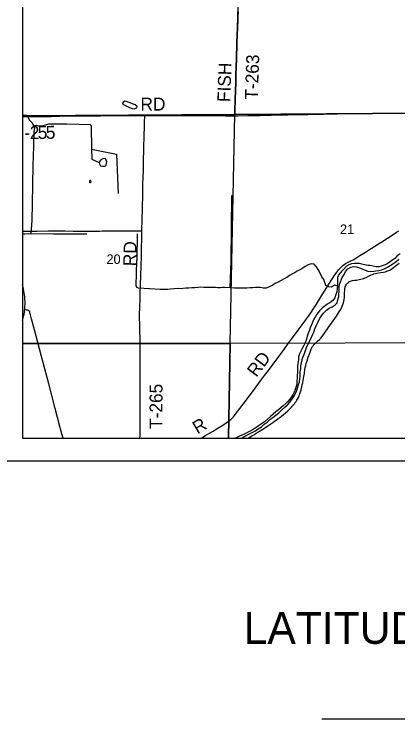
# Model space of a CAD drawing. Extents: x 0 to 34, y 0 to 22.
# Drawn here: x 2.063 to 3.748, y 12.866 to 15.963 of the extents above; entities that cross this region are included whole.
import ezdxf

# ---------------------------------------------------------------- set-up
doc = ezdxf.new("R2010")
doc.units = 0
for name, color, linetype in [('Default', 7, 'Continuous'), ('GM_X_County_Road', 7, 'Continuous'), ('GM_X_County_Road_Text', 7, 'Continuous'), ('GM_X_Major_River', 7, 'Continuous'), ('GM_X_Minor_Lake', 7, 'Continuous'), ('GM_X_Minor_River', 7, 'Continuous'), ('GM_X_Section', 7, 'Continuous'), ('GM_X_Section_Text', 7, 'Continuous'), ('GM_X_State_Route', 7, 'Continuous'), ('GM_X_Township_Road', 7, 'Continuous'), ('GM_X_Township_Road_Text', 7, 'Continuous'), ('SH_Cut_Line', 7, 'Continuous'), ('SH_Data', 7, 'Continuous'), ('SH_Text', 7, 'Continuous')]:
    doc.layers.add(name, color=color, linetype=linetype)

msp = doc.modelspace()

# ---------------------------------------------------------------- linework, layer by layer
at = {"layer": 'Default'}
for points in [[(2.1, 20.9), (2.1, 15.5125), (2.1335, 15.5129), (2.1815, 15.5136), (2.2258, 15.5141), (2.2457, 15.5144), (2.2639, 15.5151), (2.2983, 15.5158), (2.3231, 15.516), (2.3339, 15.516), (2.343, 15.516), (2.3476, 15.5161), (2.3661, 15.5163), (2.3832, 15.5166), (2.4025, 15.5166), (2.4222, 15.5167), (2.4426, 15.5165), (2.4906, 15.5172), (2.5125, 15.5174), (2.5402, 15.5177), (2.5775, 15.5177), (2.6024, 15.5175), (2.6303, 15.5178), (2.6364, 15.5178), (2.6552, 15.518), (2.719, 15.5177), (2.7423, 15.5176), (2.7734, 15.5174), (2.8138, 15.5174), (2.8667, 15.5172), (2.9429, 15.5172), (2.9911, 15.517), (3.0253, 15.5169), (3.0312, 15.5169), (3.0315, 15.5224), (3.0323, 15.5411), (3.0338, 15.5877), (3.0363, 15.6623), (3.0371, 15.6965), (3.038, 15.7308), (3.0394, 15.7681), (3.0416, 15.8334), (3.043, 15.877), (3.0437, 15.8954), (3.0439, 15.9013), (3.0443, 15.9135), (3.0446, 15.9228), (3.0452, 15.9414), (3.0454, 15.9508), (3.0461, 15.9726)], [(3.0461, 15.9726), (3.0454, 15.9508), (3.0452, 15.9414), (3.0446, 15.9228), (3.0443, 15.9135), (3.0439, 15.9013), (3.0437, 15.8954), (3.043, 15.877), (3.0416, 15.8334), (3.0394, 15.7681), (3.038, 15.7308), (3.0371, 15.6965), (3.0363, 15.6623), (3.0338, 15.5877), (3.0323, 15.5411), (3.0315, 15.5224), (3.0312, 15.5169), (3.0253, 15.5169), (2.9911, 15.517), (2.9429, 15.5172), (2.8667, 15.5172), (2.8138, 15.5174), (2.7734, 15.5174), (2.7423, 15.5176), (2.719, 15.5177), (2.6552, 15.518), (2.6364, 15.5178), (2.6303, 15.5178), (2.6024, 15.5175), (2.5775, 15.5177), (2.5402, 15.5177), (2.5125, 15.5174), (2.4906, 15.5172), (2.4426, 15.5165), (2.4222, 15.5167), (2.4025, 15.5166), (2.3832, 15.5166), (2.3661, 15.5163), (2.3476, 15.5161), (2.343, 15.516), (2.3339, 15.516), (2.3231, 15.516), (2.2983, 15.5158), (2.2639, 15.5151), (2.2457, 15.5144), (2.2258, 15.5141), (2.1815, 15.5136), (2.1335, 15.5129), (2.1, 15.5125), (2.1, 14.1), (7.0155, 14.1)]]:
    msp.add_lwpolyline(points, dxfattribs=at)
for points in [[(2.1, 16.5162), (2.1, 15.5152), (3.0319, 15.521), (3.0627, 16.5204)], [(2.1, 15.5152), (2.1, 14.516), (3.0117, 14.5162), (3.0319, 15.521)], [(2.1, 14.516), (2.1, 14.1), (3.005, 14.1), (3.0117, 14.5162)], [(3.005, 14.1), (4.0075, 14.1), (4.0206, 14.5179), (3.0117, 14.5162)]]:
    msp.add_lwpolyline(points, close=True, dxfattribs=at)
at = {"layer": 'GM_X_County_Road'}
for points in [[(2.8851, 14.1), (2.9051, 14.112), (2.9365, 14.1309), (2.954, 14.1416), (2.9788, 14.157), (2.9944, 14.1672), (3.0041, 14.1738), (3.01, 14.1783), (3.0148, 14.1823), (3.0198, 14.1869), (3.0258, 14.1931), (3.031, 14.1992), (3.0387, 14.2089), (3.0539, 14.2294), (3.0686, 14.2494), (3.0871, 14.2736), (3.0994, 14.29), (3.1142, 14.3093), (3.1376, 14.3406), (3.1495, 14.3566), (3.1628, 14.3746), (3.1796, 14.397), (3.2, 14.4244), (3.2251, 14.4585), (3.247, 14.4879), (3.2669, 14.515), (3.2943, 14.5519), (3.3102, 14.5734), (3.3274, 14.597), (3.3443, 14.6201), (3.3557, 14.6363), (3.3656, 14.6506), (3.3763, 14.6667), (3.3903, 14.6887), (3.4133, 14.7256), (3.4289, 14.7503), (3.4453, 14.7768), (3.4611, 14.8013), (3.4716, 14.8168), (3.4816, 14.8311), (3.4872, 14.8386), (3.4928, 14.8453), (3.4971, 14.8499), (3.5016, 14.8543), (3.5069, 14.8587), (3.5124, 14.8628), (3.5182, 14.8666), (3.5237, 14.8696), (3.533, 14.8742), (3.5437, 14.8797), (3.5513, 14.8838), (3.5631, 14.8906), (3.5811, 14.9018), (3.5984, 14.9127), (3.6105, 14.9204), (3.6194, 14.926), (3.671, 14.9584), (3.6731, 14.9598), (3.7025, 14.9785), (3.7271, 14.9942), (3.7427, 15.0044), (3.7516, 15.0102)], [(2.2777, 14.1), (2.2729, 14.1179), (2.2643, 14.151), (2.2437, 14.2293), (2.2286, 14.2864), (2.2152, 14.3376), (2.1978, 14.4039), (2.1819, 14.4641), (2.1523, 14.5753), (2.1396, 14.6235), (2.1349, 14.6415), (2.1325, 14.6506), (2.1314, 14.6537), (2.1301, 14.6571), (2.1282, 14.6594), (2.125, 14.6614), (2.1221, 14.6622), (2.1186, 14.6625), (2.1154, 14.6626), (2.109, 14.6629)]]:
    msp.add_lwpolyline(points, dxfattribs=at)
at = {"layer": 'GM_X_Major_River'}
for points in [[(3.7575, 14.9091), (3.7451, 14.9003), (3.7346, 14.8888), (3.7015, 14.8652)], [(3.7015, 14.8652), (3.6919, 14.8608), (3.6793, 14.8564), (3.6659, 14.8525), (3.653, 14.8527), (3.6398, 14.8548), (3.6265, 14.8576), (3.617, 14.8586), (3.6034, 14.8618), (3.5894, 14.8647), (3.5796, 14.8664), (3.5572, 14.8667), (3.545, 14.865), (3.5324, 14.8614), (3.5224, 14.8551), (3.5108, 14.8424), (3.4992, 14.83), (3.4889, 14.8186), (3.4834, 14.8051), (3.4831, 14.7934), (3.4829, 14.7805), (3.4829, 14.7678), (3.4822, 14.757), (3.4793, 14.743), (3.4757, 14.7301), (3.4709, 14.7165), (3.4627, 14.7045), (3.4489, 14.6945), (3.4382, 14.6882), (3.4282, 14.6807), (3.4166, 14.6722), (3.4035, 14.6587), (3.3919, 14.6448), (3.3861, 14.6347), (3.379, 14.623), (3.3739, 14.6124), (3.3681, 14.598), (3.3636, 14.5845), (3.3604, 14.5743), (3.3545, 14.5615), (3.3501, 14.5483), (3.3465, 14.5339), (3.3406, 14.518), (3.3347, 14.506), (3.3284, 14.4939), (3.3221, 14.4819), (3.3159, 14.4694), (3.3123, 14.4563), (3.3113, 14.4437), (3.3084, 14.4281), (3.3074, 14.4171), (3.3069, 14.4073), (3.3075, 14.3955), (3.3066, 14.386), (3.3061, 14.3762), (3.3063, 14.3636), (3.3049, 14.3519), (3.304, 14.3394), (3.3011, 14.3269), (3.2975, 14.3136), (3.2928, 14.3019), (3.2861, 14.2906), (3.2775, 14.2767), (3.2656, 14.2625), (3.257, 14.2527), (3.2439, 14.2412), (3.2359, 14.2349), (3.2235, 14.2245), (3.2124, 14.2151), (3.2009, 14.205), (3.1893, 14.1942), (3.1758, 14.1837), (3.1624, 14.1718), (3.1493, 14.1618), (3.1366, 14.1532), (3.1247, 14.1451), (3.1094, 14.1358), (3.0998, 14.1306), (3.0879, 14.1247), (3.0757, 14.1185), (3.0627, 14.1122), (3.0497, 14.1063), (3.0378, 14.1008), (3.0353, 14.1)], [(3.5789, 14.8474), (3.5917, 14.8434), (3.6042, 14.8375), (3.6167, 14.8331), (3.6295, 14.8324), (3.6421, 14.8339), (3.6516, 14.8349), (3.6642, 14.8366), (3.6771, 14.8394), (3.6901, 14.8453), (3.7024, 14.8508), (3.7146, 14.8578), (3.7265, 14.8656)], [(3.7265, 14.8656), (3.74, 14.8761), (3.752, 14.8857)], [(3.0619, 14.1), (3.0647, 14.1011), (3.0763, 14.1078), (3.0882, 14.1149), (3.0996, 14.1204), (3.1111, 14.1266), (3.123, 14.1325), (3.1353, 14.1407), (3.1488, 14.1496), (3.1614, 14.1604), (3.1737, 14.1705), (3.186, 14.1809), (3.1983, 14.1902), (3.2122, 14.201), (3.2249, 14.2107), (3.2376, 14.2227), (3.2511, 14.2354), (3.2634, 14.2462), (3.2742, 14.2578), (3.2831, 14.2698), (3.2913, 14.2826), (3.2966, 14.2928), (3.3031, 14.3063), (3.3075, 14.3199), (3.3119, 14.3351), (3.3159, 14.3471), (3.318, 14.3608), (3.3189, 14.3703), (3.3191, 14.3813), (3.3196, 14.3908), (3.3217, 14.4036), (3.3226, 14.4162), (3.3235, 14.4256), (3.3264, 14.4358), (3.3296, 14.451), (3.3348, 14.4638), (3.3395, 14.4755), (3.3439, 14.4891), (3.3471, 14.4989), (3.3522, 14.5099), (3.3573, 14.52), (3.3632, 14.5302), (3.3687, 14.5434), (3.373, 14.5532), (3.3785, 14.5657), (3.3833, 14.5793), (3.391, 14.5964), (3.3963, 14.6079), (3.4045, 14.6245), (3.4123, 14.6369), (3.4212, 14.6493), (3.4343, 14.6613), (3.447, 14.6709), (3.46, 14.6772), (3.4721, 14.6848), (3.481, 14.6946), (3.4848, 14.7068), (3.4881, 14.7227), (3.489, 14.7326), (3.4896, 14.7457), (3.4898, 14.7572), (3.4907, 14.7675), (3.4935, 14.7792), (3.5041, 14.806), (3.5116, 14.8188), (3.5183, 14.8312), (3.5276, 14.844), (3.541, 14.8506), (3.5528, 14.8535), (3.5657, 14.8529), (3.5789, 14.8474)]]:
    msp.add_lwpolyline(points, dxfattribs=at)
at = {"layer": 'GM_X_Minor_Lake'}
for p, q in [((2.5829, 15.5692), (2.5748, 15.5713)), ((2.4422, 15.2965), (2.4516, 15.2947)), ((2.3933, 15.227), (2.3941, 15.2236))]:
    msp.add_line(p, q, dxfattribs=at)
for points in [[(2.5748, 15.5713), (2.5678, 15.5738), (2.5569, 15.5791), (2.5498, 15.5808), (2.5417, 15.5765), (2.5388, 15.5678), (2.5463, 15.5642), (2.5702, 15.5525), (2.5807, 15.5484), (2.5894, 15.547), (2.6013, 15.5508), (2.6034, 15.5565), (2.5949, 15.5643), (2.5829, 15.5692)], [(2.4516, 15.2947), (2.4623, 15.2947), (2.4678, 15.2992), (2.4708, 15.3131), (2.464, 15.3282), (2.4522, 15.3266), (2.4418, 15.3204), (2.437, 15.3107), (2.4383, 15.3046), (2.4422, 15.2965)], [(2.3941, 15.2236), (2.3973, 15.2229), (2.4019, 15.2254), (2.3998, 15.2323), (2.3956, 15.2316), (2.3933, 15.2294), (2.3933, 15.227)]]:
    msp.add_lwpolyline(points, dxfattribs=at)
at = {"layer": 'GM_X_Minor_River'}
for points in [[(2.1, 15.5185), (2.1195, 15.5186), (2.1248, 15.5075), (2.131, 15.4963), (2.1402, 15.4861), (2.15, 15.4706), (2.1531, 15.4603), (2.1494, 15.449), (2.1486, 15.3809), (2.1458, 15.2985), (2.1434, 15.2126), (2.1415, 15.131), (2.1401, 15.0561), (2.1365, 14.9984)], [(2.15, 15.4706), (2.1546, 15.4735), (2.1615, 15.4745), (2.169, 15.4716), (2.1773, 15.4714), (2.1899, 15.474), (2.201, 15.4764), (2.2156, 15.4805), (2.2432, 15.4801), (2.296, 15.4809), (2.3984, 15.4772), (2.4016, 15.4699), (2.4029, 15.3687), (2.4043, 15.3249), (2.437, 15.3107)], [(2.4029, 15.3687), (2.5124, 15.3481), (2.5192, 15.1741)], [(3.0164, 14.8785), (3.019, 15.1657)], [(2.1, 14.9977), (2.1107, 14.9976), (2.1365, 14.9984), (2.236, 14.9971), (2.3821, 14.9974)], [(2.6034, 14.9968), (2.6012, 14.8801)], [(2.7052, 14.7533), (2.6089, 14.7584), (2.6029, 14.7616), (2.5984, 14.7685), (2.6012, 14.8801)], [(3.4829, 14.7678), (3.4691, 14.7717), (3.4564, 14.7637), (3.4431, 14.7641), (3.4315, 14.7702), (3.4277, 14.784), (3.4227, 14.797), (3.4147, 14.809), (3.409, 14.8213), (3.3974, 14.8407), (3.3905, 14.853), (3.3806, 14.8647), (3.3673, 14.8655), (3.3543, 14.8613), (3.3412, 14.8533), (3.3307, 14.8464), (3.3172, 14.8388), (3.3064, 14.8334), (3.2967, 14.828), (3.2855, 14.8215), (3.2728, 14.8143), (3.26, 14.8059), (3.2453, 14.7976), (3.2357, 14.7922), (3.2222, 14.7854), (3.2098, 14.7793), (3.1959, 14.7709), (3.1824, 14.7641), (3.1693, 14.7592), (3.1564, 14.7584), (3.1443, 14.761), (3.1326, 14.7618), (3.1223, 14.7617), (3.1097, 14.7605), (3.0976, 14.7605), (3.085, 14.7593), (3.0721, 14.759), (3.0573, 14.759), (3.0428, 14.7587), (3.0307, 14.759), (3.0166, 14.7602), (2.9874, 14.761), (2.9779, 14.7609), (2.9672, 14.7605), (2.957, 14.7604), (2.9467, 14.7611), (2.9327, 14.7615), (2.9213, 14.7611), (2.9103, 14.7618), (2.8959, 14.7622), (2.8833, 14.7629), (2.8696, 14.7618), (2.8567, 14.7607), (2.8426, 14.7596), (2.8304, 14.7588), (2.8167, 14.758), (2.8045, 14.7572), (2.7927, 14.7564), (2.779, 14.7565), (2.7657, 14.7553), (2.7501, 14.7539), (2.7375, 14.7535), (2.7261, 14.7531), (2.7159, 14.7534), (2.7052, 14.7533)], [(3.0118, 14.7603), (3.0164, 14.8785)]]:
    msp.add_lwpolyline(points, dxfattribs=at)
at = {"layer": 'GM_X_Section'}
for points in [[(3.0627, 16.5204), (4.0656, 16.5335), (4.0396, 15.5284), (3.0319, 15.521)], [(4.0396, 15.5284), (4.0206, 14.5179), (3.0117, 14.5162), (3.0319, 15.521)]]:
    msp.add_lwpolyline(points, close=True, dxfattribs=at)
at = {"layer": 'GM_X_State_Route'}
msp.add_lwpolyline([(2.1, 14.6166), (2.1019, 14.6232), (2.1044, 14.6338), (2.1065, 14.6445), (2.1081, 14.6553), (2.109, 14.6629), (2.1094, 14.6662), (2.1103, 14.6771), (2.1108, 14.688), (2.1108, 14.6989), (2.1104, 14.7098), (2.1095, 14.7207), (2.1082, 14.7315), (2.1063, 14.7438), (2.1043, 14.7545), (2.1012, 14.7682), (2.1, 14.773)], dxfattribs=at)
at = {"layer": 'GM_X_Township_Road'}
for points in [[(3.0314, 15.5164), (3.0317, 15.5219), (3.0325, 15.5405), (3.034, 15.5872), (3.0366, 15.6618), (3.0373, 15.696), (3.0383, 15.7302), (3.0397, 15.7676), (3.0418, 15.8329), (3.0432, 15.8764), (3.0439, 15.8948), (3.0441, 15.9007), (3.0446, 15.9129), (3.0448, 15.9222), (3.0454, 15.9409), (3.0457, 15.9502), (3.0463, 15.972)], [(2.1, 15.5119), (2.1337, 15.5124), (2.1818, 15.513), (2.226, 15.5136), (2.2459, 15.5139), (2.2642, 15.5146), (2.2986, 15.5152), (2.3233, 15.5154), (2.3342, 15.5154), (2.3433, 15.5154), (2.3478, 15.5156), (2.3663, 15.5158), (2.3834, 15.516), (2.4027, 15.5161), (2.4224, 15.5161), (2.4428, 15.5159), (2.4909, 15.5166), (2.5127, 15.5168), (2.5305, 15.517)], [(2.5305, 15.517), (2.5404, 15.5171), (2.5777, 15.5171), (2.6026, 15.517), (2.6306, 15.5172), (2.6366, 15.5173)], [(2.6244, 15.0111), (2.6244, 15.0132), (2.6267, 15.1079), (2.627, 15.1219), (2.6277, 15.1577), (2.6277, 15.1732), (2.6276, 15.1841), (2.6276, 15.1918), (2.6278, 15.2027), (2.6285, 15.2198), (2.6294, 15.2415), (2.6304, 15.2804), (2.6309, 15.3037), (2.6316, 15.3332), (2.632, 15.3518), (2.6322, 15.3611), (2.6326, 15.3767), (2.6342, 15.4264), (2.6353, 15.4683), (2.6359, 15.4916), (2.6365, 15.5117), (2.6366, 15.5173)], [(2.6366, 15.5173), (2.6554, 15.5174), (2.7192, 15.5171), (2.7425, 15.517), (2.7736, 15.5169), (2.814, 15.5168), (2.8669, 15.5167), (2.9431, 15.5166), (2.9913, 15.5165), (3.0255, 15.5164), (3.0314, 15.5164)], [(3.0314, 15.5164), (3.0473, 15.5163), (3.0892, 15.5169), (3.1219, 15.5176), (3.1436, 15.5179), (3.1624, 15.5182), (3.1918, 15.5189), (3.2369, 15.5198), (3.2648, 15.5204), (3.3069, 15.5211), (3.352, 15.5216), (3.4218, 15.5235), (3.5415, 15.5257), (3.582, 15.5262), (3.6333, 15.5268), (3.6908, 15.5275), (3.7545, 15.5278), (3.8105, 15.5282), (3.9131, 15.5284), (3.9567, 15.5287), (3.9987, 15.5291), (4.0375, 15.5293), (4.0423, 15.5293)], [(2.1, 15.0091), (2.1116, 15.0092), (2.1644, 15.0095), (2.214, 15.0102), (2.2513, 15.0101), (2.2854, 15.0099), (2.3226, 15.0096), (2.3351, 15.0096), (2.3816, 15.0095), (2.4249, 15.0096), (2.4373, 15.0097), (2.4497, 15.0099), (2.4621, 15.0101), (2.4838, 15.0102), (2.4962, 15.0101), (2.5116, 15.0101), (2.5146, 15.0101), (2.5207, 15.0103), (2.5268, 15.0104), (2.5391, 15.0105), (2.5515, 15.0107), (2.5825, 15.0109), (2.6104, 15.011), (2.6198, 15.0111), (2.6244, 15.0111)], [(2.6157, 14.1), (2.6158, 14.1105), (2.6161, 14.1385), (2.6164, 14.1898), (2.6163, 14.2364), (2.6165, 14.2831), (2.6166, 14.3173), (2.6166, 14.4027), (2.6165, 14.4463), (2.6164, 14.4882), (2.6163, 14.5115), (2.6158, 14.5395), (2.6152, 14.569), (2.6145, 14.6047), (2.6142, 14.6218), (2.614, 14.6327), (2.6139, 14.642), (2.6141, 14.6513), (2.6145, 14.6652), (2.6149, 14.6776), (2.6159, 14.704), (2.617, 14.7382), (2.6183, 14.7739), (2.6195, 14.8127), (2.6207, 14.8578), (2.6216, 14.8998), (2.6244, 15.0111)], [(3.0902, 14.1), (3.0925, 14.1011), (3.1074, 14.1095), (3.1181, 14.1159), (3.126, 14.1208), (3.1366, 14.1273), (3.155, 14.139), (3.1641, 14.1449), (3.177, 14.1536), (3.1988, 14.1685), (3.2102, 14.1765), (3.214, 14.1792), (3.2229, 14.1855), (3.2279, 14.1891), (3.2316, 14.192), (3.2437, 14.2018), (3.2544, 14.2108), (3.2648, 14.2201), (3.2749, 14.2298), (3.2804, 14.2354), (3.2845, 14.2401), (3.2887, 14.2447), (3.2936, 14.2508), (3.2973, 14.2558), (3.3008, 14.261), (3.3042, 14.2662), (3.3066, 14.2703), (3.311, 14.2786), (3.3141, 14.2857), (3.3163, 14.2916), (3.3173, 14.2945), (3.3202, 14.3034), (3.3228, 14.3124), (3.3259, 14.3244), (3.3284, 14.335), (3.33, 14.3426), (3.3325, 14.3548), (3.3352, 14.3702), (3.3375, 14.384), (3.3401, 14.4008), (3.3427, 14.4145), (3.3437, 14.4191), (3.346, 14.4281), (3.3495, 14.4399), (3.3548, 14.4561), (3.361, 14.4737), (3.366, 14.4868), (3.3678, 14.491), (3.3705, 14.4965), (3.3736, 14.5018), (3.3771, 14.5069), (3.38, 14.5104), (3.3864, 14.5171), (3.3952, 14.5258), (3.4032, 14.5329), (3.4093, 14.5395), (3.4143, 14.5453), (3.4195, 14.5517), (3.4323, 14.5701), (3.4496, 14.595), (3.4634, 14.6147), (3.4782, 14.6356), (3.4879, 14.6504), (3.493, 14.6585), (3.497, 14.6654), (3.5002, 14.6723), (3.5037, 14.6794), (3.5063, 14.6866), (3.5086, 14.6942), (3.5109, 14.7016), (3.5121, 14.7093), (3.5132, 14.717), (3.5138, 14.7266), (3.5144, 14.7343), (3.5144, 14.7375), (3.5145, 14.7499), (3.5147, 14.7545), (3.5152, 14.759), (3.5159, 14.762), (3.5168, 14.7649), (3.5185, 14.7691), (3.5206, 14.7731), (3.5223, 14.7756), (3.5252, 14.7791), (3.5273, 14.7813), (3.5308, 14.7842), (3.5334, 14.7859), (3.536, 14.7874), (3.5402, 14.7892), (3.5445, 14.7908), (3.549, 14.7919), (3.5579, 14.7932), (3.5671, 14.7945), (3.5778, 14.7962), (3.5856, 14.7978), (3.5918, 14.7993), (3.5976, 14.8011), (3.6035, 14.8034), (3.6093, 14.8057), (3.6191, 14.8107), (3.6247, 14.8138), (3.6306, 14.8166), (3.6371, 14.8191), (3.6431, 14.8212), (3.6491, 14.823), (3.655, 14.8242), (3.6717, 14.8271), (3.6856, 14.8293), (3.6932, 14.8308), (3.6993, 14.8326), (3.7037, 14.8342), (3.708, 14.836), (3.7122, 14.8382), (3.7177, 14.8413), (3.7229, 14.8447), (3.7292, 14.8494), (3.7365, 14.8552), (3.7412, 14.8589), (3.7474, 14.8635), (3.7537, 14.8678)]]:
    msp.add_lwpolyline(points, dxfattribs=at)
at = {"layer": 'SH_Cut_Line'}
msp.add_lwpolyline([(2.1, 20.9), (2.1, 14.1), (7.0155, 14.1)], dxfattribs=at)
at = {"layer": 'SH_Data'}
for p, q in [((2.1, 20.9), (2.1, 14.1)), ((2.1, 14.1), (8.9, 14.1)), ((2.1, 14.1), (2.1, 14.1)), ((2, 14), (9, 14)), ((3.4138, 12.866), (4.6554, 12.866))]:
    msp.add_line(p, q, dxfattribs=at)

# ---------------------------------------------------------------- texts
at = {"layer": 'GM_X_County_Road_Text'}
for s, height, rotation, p in [('RD', 0.05682, 53.0322, (3.1265, 14.3644)), ('R', 0.0568, 30.6197, (2.8677, 14.1159))]:
    msp.add_text(s, height=height, rotation=rotation, dxfattribs=at).set_placement(p)
at = {"layer": 'GM_X_Section_Text'}
for s, p in [('21', (3.4938, 14.9966)), ('20', (2.4684, 14.8651))]:
    msp.add_text(s, height=0.04186, rotation=0, dxfattribs=at).set_placement(p)
at = {"layer": 'GM_X_Township_Road_Text'}
for s, height, rotation, p in [('T-263', 0.05682, 88.0353, (3.1328, 15.586)), ('FISH', 0.05682, 88.0975, (3.0119, 15.5755)), ('RD', 0.05682, 0, (2.6176, 15.539)), ('2', 0.0568, 0.6388, (2.132, 15.4137)), ('5', 0.0568, 0.7651, (2.1671, 15.4141)), ('5', 0.0568, 1.291, (2.2027, 15.4146)), ('-', 0.0568, 0.5992, (2.1086, 15.4135)), ('RD', 0.05682, 88.5306, (2.5986, 14.8545)), ('T-265', 0.05682, 90, (2.7145, 14.14))]:
    msp.add_text(s, height=height, rotation=rotation, dxfattribs=at).set_placement(p)
at = {"layer": 'SH_Text'}
msp.add_text('LATITUDE:  N41°24\'33"     LONGITUDE:  W83°27\'25"', height=0.14, dxfattribs=at).set_placement((3.071, 13.1958))

doc.saveas('drawing.dxf')
